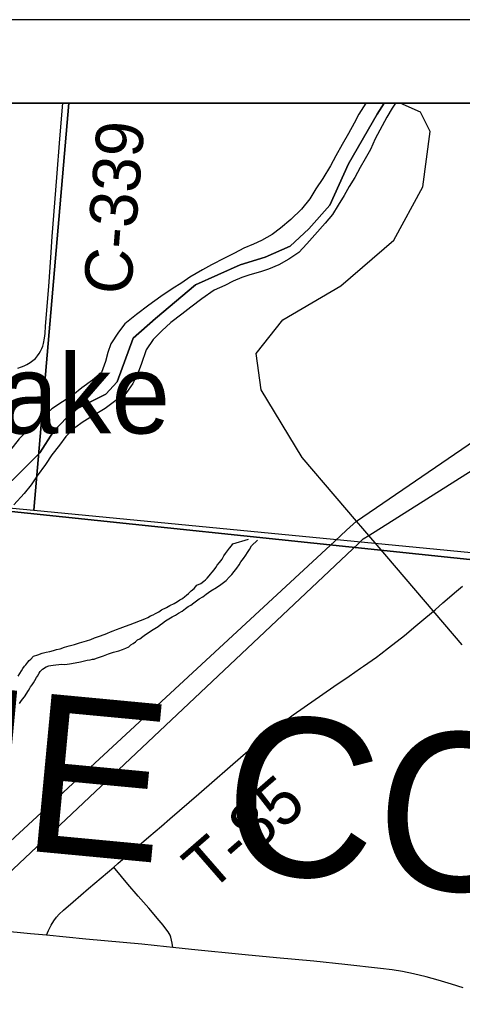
# Model space of a CAD drawing. Extents: x 0 to 34, y 0 to 22.
# Drawn here: x 25.311 to 25.841, y 19.186 to 20.362 of the extents above; entities that cross this region are included whole.
import ezdxf

# ---------------------------------------------------------------- set-up
doc = ezdxf.new("R2010")
doc.units = 0
for name, color, linetype in [('GM_X_County_Road', 7, 'Continuous'), ('GM_X_County_Road_Text', 7, 'Continuous'), ('GM_X_County_Text', 7, 'Continuous'), ('GM_X_Major_River', 7, 'Continuous'), ('GM_X_Minor_Lake_Text', 7, 'Continuous'), ('GM_X_Minor_River', 7, 'Continuous'), ('GM_X_Rail_Line', 7, 'Continuous'), ('GM_X_State_Route', 7, 'Continuous'), ('GM_X_Township_Road', 7, 'Continuous'), ('GM_X_Township_Road_Text', 7, 'Continuous'), ('SH_Border', 7, 'Continuous'), ('SH_Data', 7, 'Continuous')]:
    doc.layers.add(name, color=color, linetype=linetype)

msp = doc.modelspace()

# ---------------------------------------------------------------- linework, layer by layer
at = {"layer": 'GM_X_County_Road'}
for points in [[(25.3703, 20.2618), (24.3175, 20.2618), (24.2811, 19.8754), (24.2808, 19.8728), (25.3283, 19.7746)], [(26.3766, 20.2618), (25.3703, 20.2618), (25.3283, 19.7746), (26.3216, 19.6787)]]:
    msp.add_lwpolyline(points, close=True, dxfattribs=at)
msp.add_lwpolyline([(25.309, 19.9449), (25.3133, 19.9464), (25.3166, 19.9477), (25.3199, 19.9493), (25.3238, 19.9515), (25.3269, 19.9538), (25.3302, 19.9563), (25.3328, 19.9594), (25.3347, 19.9621), (25.3363, 19.9649), (25.3379, 19.9683), (25.3388, 19.971), (25.3397, 19.9744), (25.3409, 19.9806), (25.3416, 19.9861), (25.3423, 19.9948), (25.346, 20.0426), (25.3484, 20.0773), (25.3502, 20.1021), (25.3556, 20.1728), (25.3593, 20.219), (25.3631, 20.2618)], dxfattribs=at)
at = {"layer": 'GM_X_Major_River'}
for points in [[(25.7611, 20.2618), (25.7571, 20.2557), (25.7507, 20.2452), (25.7368, 20.219), (25.7311, 20.2066), (25.7248, 20.1953), (25.7188, 20.1849), (25.7124, 20.1729), (25.7057, 20.162), (25.6997, 20.1515), (25.6922, 20.1399), (25.6855, 20.1287), (25.6769, 20.1183), (25.6644, 20.1042), (25.655, 20.0934), (25.6452, 20.083), (25.6332, 20.075), (25.6213, 20.0684), (25.609, 20.0634), (25.5995, 20.0599), (25.5868, 20.0564), (25.5773, 20.0532), (25.5669, 20.0489), (25.5569, 20.0435), (25.5442, 20.0381), (25.5292, 20.0278), (25.516, 20.0179), (25.5055, 20.0095), (25.492, 19.9992), (25.4815, 19.9896), (25.471, 19.9792), (25.4627, 19.9665), (25.4565, 19.9492), (25.4521, 19.9375), (25.4465, 19.9262), (25.4382, 19.9143), (25.4262, 19.9059), (25.4134, 19.8963), (25.3995, 19.8879), (25.3872, 19.8803), (25.3771, 19.8733), (25.3666, 19.8629), (25.3588, 19.8525), (25.3497, 19.841), (25.3422, 19.8294), (25.3324, 19.8159), (25.3249, 19.8051), (25.3167, 19.7947), (25.3042, 19.7813)], [(25.7253, 20.2618), (25.7253, 20.2618), (25.717, 20.2487), (25.7114, 20.2378), (25.7047, 20.2255), (25.6971, 20.2124), (25.6896, 20.1989), (25.6832, 20.1869), (25.6741, 20.1719), (25.6658, 20.1592), (25.6586, 20.1473), (25.6484, 20.135), (25.6356, 20.1228), (25.6232, 20.1124), (25.6135, 20.1047), (25.6008, 20.0974), (25.5912, 20.0931), (25.5797, 20.0885), (25.5685, 20.0823), (25.5562, 20.0762), (25.5408, 20.0682), (25.53, 20.0624), (25.515, 20.0537), (25.5053, 20.0467), (25.4938, 20.0398), (25.4803, 20.0306)], [(25.4803, 20.0306), (25.466, 20.0203), (25.4512, 20.0089), (25.4373, 19.9979), (25.4294, 19.9878), (25.4203, 19.974), (25.4167, 19.9635), (25.4141, 19.9529), (25.4092, 19.9397), (25.3984, 19.9305), (25.3856, 19.9213), (25.3747, 19.9125), (25.3624, 19.9044), (25.3496, 19.896), (25.3356, 19.8827), (25.3224, 19.8713), (25.3108, 19.8602), (25.299, 19.8453), (25.2914, 19.8299), (25.2872, 19.8167), (25.2824, 19.8043), (25.2749, 19.7923), (25.2653, 19.788), (25.243, 19.7721)]]:
    msp.add_lwpolyline(points, dxfattribs=at)
at = {"layer": 'GM_X_Minor_River'}
for points in [[(25.4165, 19.6277), (25.4199, 19.6292), (25.4233, 19.6303), (25.4271, 19.6318), (25.4314, 19.6336), (25.4378, 19.6358), (25.4436, 19.6379), (25.4611, 19.6449), (25.4646, 19.6463), (25.468, 19.6482), (25.4711, 19.6496), (25.4738, 19.6511), (25.4776, 19.6533), (25.481, 19.6556), (25.4868, 19.6585), (25.491, 19.6607), (25.496, 19.6629), (25.5002, 19.6655), (25.5029, 19.6674), (25.5063, 19.6692), (25.509, 19.6714), (25.5109, 19.6729), (25.5132, 19.6752), (25.5163, 19.6782), (25.5202, 19.6811), (25.5233, 19.6849), (25.5282, 19.6871), (25.5317, 19.6897), (25.5336, 19.6916), (25.5356, 19.6934), (25.5379, 19.696), (25.5398, 19.6983), (25.5417, 19.7005), (25.5441, 19.7032), (25.546, 19.7062), (25.5476, 19.7088), (25.5503, 19.7122), (25.5534, 19.7163), (25.5557, 19.7201), (25.5577, 19.7231), (25.56, 19.7261), (25.5623, 19.7294), (25.5646, 19.7321), (25.5662, 19.7343), (25.5849, 19.7399)], [(25.447, 19.6151), (25.4497, 19.6173), (25.4524, 19.6196), (25.4551, 19.621), (25.4585, 19.6236), (25.462, 19.6259), (25.4651, 19.6281), (25.4689, 19.6307), (25.4769, 19.6355), (25.4792, 19.6374), (25.4823, 19.6396), (25.4858, 19.6422), (25.4896, 19.6448), (25.4938, 19.647), (25.4977, 19.6492), (25.5015, 19.6514), (25.5057, 19.654), (25.5099, 19.657), (25.513, 19.6596), (25.5161, 19.6611), (25.5195, 19.6637), (25.523, 19.6663), (25.526, 19.6685), (25.5303, 19.6711), (25.5345, 19.6744), (25.5402, 19.6782), (25.5468, 19.6822), (25.5521, 19.6859), (25.5583, 19.6908), (25.5621, 19.6945), (25.5652, 19.6979), (25.5679, 19.7012), (25.571, 19.7054), (25.5738, 19.7095), (25.5761, 19.7129), (25.5792, 19.717), (25.5819, 19.7208), (25.5839, 19.7242), (25.5862, 19.7279), (25.5886, 19.7321), (25.5958, 19.7389)], [(25.3093, 19.5763), (25.3113, 19.5793), (25.3136, 19.5827), (25.3152, 19.5853), (25.3171, 19.588), (25.3187, 19.5898), (25.321, 19.5928), (25.3225, 19.5947), (25.3245, 19.5966), (25.3279, 19.5999), (25.3329, 19.6018), (25.3383, 19.6036), (25.3428, 19.605), (25.3474, 19.6057), (25.3516, 19.6068), (25.3554, 19.6082), (25.3596, 19.6089), (25.3649, 19.6107), (25.3707, 19.6125), (25.3768, 19.614), (25.3829, 19.6161), (25.3912, 19.6183), (25.3966, 19.6201), (25.4008, 19.6219), (25.4046, 19.623), (25.4081, 19.6245), (25.4111, 19.6256), (25.4134, 19.6263), (25.4165, 19.6277)], [(25.3111, 19.5436), (25.3127, 19.5459), (25.3146, 19.5485), (25.3169, 19.5515), (25.322, 19.559), (25.3235, 19.5617), (25.3243, 19.5635), (25.3263, 19.5658), (25.3278, 19.568), (25.3294, 19.5711), (25.3313, 19.5744), (25.3325, 19.5763), (25.3345, 19.5797), (25.336, 19.5816), (25.3387, 19.5846), (25.3429, 19.5872), (25.346, 19.5883), (25.3486, 19.589), (25.3513, 19.5893), (25.3547, 19.5896), (25.3582, 19.59), (25.3616, 19.5903), (25.3654, 19.5902), (25.3711, 19.5909), (25.3775, 19.5919), (25.384, 19.5933), (25.392, 19.5951), (25.3958, 19.5958), (25.3985, 19.5965), (25.4004, 19.5965), (25.4031, 19.5976), (25.4069, 19.599), (25.4115, 19.6005), (25.4176, 19.6027), (25.4237, 19.6048), (25.4298, 19.6066), (25.4344, 19.6081), (25.4382, 19.6095), (25.442, 19.6114), (25.4443, 19.6136), (25.447, 19.6151)]]:
    msp.add_lwpolyline(points, dxfattribs=at)
at = {"layer": 'GM_X_Rail_Line'}
for p, q in [((25.729, 19.7446), (26.549, 20.2618)), ((25.739, 19.7329), (25.729, 19.7446)), ((25.8406, 19.6138), (25.739, 19.7329))]:
    msp.add_line(p, q, dxfattribs=at)
for points in [[(25.7145, 19.7615), (25.689, 19.7914), (25.6493, 19.838), (25.6002, 19.9189), (25.5944, 19.9622), (25.6262, 20.0027), (25.6955, 20.0431), (25.759, 20.098), (25.7937, 20.1616), (25.8023, 20.228), (25.7908, 20.2511), (25.7664, 20.2618)], [(25.7145, 19.7615), (26.2866, 20.1528), (26.4666, 20.2618)], [(25.6884, 19.7377), (25.7025, 19.7507), (25.7145, 19.7615)], [(25.729, 19.7446), (25.7218, 19.753), (25.7145, 19.7615)], [(22.5164, 16.9354), (22.6202, 16.9977), (23.2863, 17.3926), (23.9265, 17.9846), (25.2894, 19.3687), (25.6884, 19.7377)], [(22.5164, 16.4015), (22.604, 16.4732), (22.6804, 16.5359), (22.9964, 16.9071), (23.3912, 17.4049), (25.2192, 19.2663), (25.7166, 19.735)], [(25.7166, 19.735), (25.7222, 19.7403), (25.729, 19.7446)]]:
    msp.add_lwpolyline(points, dxfattribs=at)
at = {"layer": 'GM_X_State_Route'}
msp.add_lwpolyline([(25.8418, 19.2032), (25.8282, 19.2077), (25.8122, 19.2125), (25.7978, 19.2163), (25.7827, 19.2198), (25.7693, 19.2225), (25.7571, 19.2245), (25.743, 19.2264), (25.7003, 19.2311), (25.6633, 19.2349), (25.6187, 19.239), (25.581, 19.2428), (25.5167, 19.2491), (25.4946, 19.2513), (25.487, 19.2521), (25.4574, 19.2552), (25.3905, 19.2614), (25.3432, 19.266), (25.3244, 19.2678), (25.2879, 19.2712)], dxfattribs=at)
at = {"layer": 'GM_X_Township_Road'}
for points in [[(25.4239, 19.3477), (25.4288, 19.3519), (25.4659, 19.3839), (25.4811, 19.3968), (25.491, 19.4053), (25.5258, 19.4354), (25.5788, 19.4815), (25.599, 19.4989), (25.6125, 19.5099), (25.6252, 19.5198), (25.6387, 19.5297), (25.6871, 19.5636), (25.7055, 19.5762), (25.7193, 19.5857), (25.7229, 19.5882), (25.7381, 19.599), (25.7436, 19.603), (25.7525, 19.6099), (25.7716, 19.6249), (25.7855, 19.6363), (25.7974, 19.6463), (25.8083, 19.6556), (25.8176, 19.6638), (25.8256, 19.6707), (25.8317, 19.6759), (25.8411, 19.684)], [(25.3432, 19.266), (25.3459, 19.2718), (25.3488, 19.2781), (25.3521, 19.2835), (25.3553, 19.2878), (25.3586, 19.2914), (25.3636, 19.2961), (25.3754, 19.3062), (25.3938, 19.322), (25.4239, 19.3477)], [(25.4946, 19.2513), (25.4937, 19.2564), (25.493, 19.2601), (25.492, 19.2637), (25.4912, 19.2661), (25.4901, 19.2682), (25.4888, 19.2702), (25.4875, 19.2723), (25.483, 19.278), (25.4783, 19.2837), (25.4657, 19.2985), (25.4531, 19.3127), (25.4407, 19.3272), (25.4256, 19.3456), (25.4239, 19.3477)]]:
    msp.add_lwpolyline(points, dxfattribs=at)
at = {"layer": 'SH_Border'}
msp.add_lwpolyline([(25.7475, 20.2618), (24.3146, 20.2618), (24.3071, 20.185), (24.2795, 19.873), (25.1948, 19.7845), (25.2129, 19.7873), (25.2376, 19.8033), (25.3026, 19.8107), (25.3354, 19.8434), (25.3518, 19.8688), (25.3756, 19.8941), (25.4144, 19.9135), (25.4278, 19.9284), (25.4471, 19.9805), (25.474, 20.0043), (25.5216, 20.0446), (25.5753, 20.0684), (25.6051, 20.0774), (25.6349, 20.0908), (25.6572, 20.1116), (25.6826, 20.1399), (25.7049, 20.1891), (25.7392, 20.2487)], close=True, dxfattribs=at)
for points in [[(29.3164, 20.2618), (25.7475, 20.2618), (25.7392, 20.2487), (25.7049, 20.1891), (25.6826, 20.1399), (25.6572, 20.1116), (25.6349, 20.0908), (25.6051, 20.0774), (25.5753, 20.0684), (25.5216, 20.0446), (25.474, 20.0043), (25.4471, 19.9805), (25.4278, 19.9284), (25.4144, 19.9135), (25.3756, 19.8941), (25.3518, 19.8688), (25.3354, 19.8434), (25.3026, 19.8107), (25.2376, 19.8033), (25.2129, 19.7873), (25.1948, 19.7845), (25.8728, 19.7133), (27.3379, 19.575)], [(29.3164, 19.3886), (27.8281, 19.5287), (27.6909, 19.5416), (27.4869, 19.5609), (27.4759, 19.5619), (27.4554, 19.5638), (27.4405, 19.5654), (27.3379, 19.575), (25.8728, 19.7133), (25.1948, 19.7845), (24.2795, 19.873)]]:
    msp.add_lwpolyline(points, dxfattribs=at)
at = {"layer": 'SH_Data'}
for p, q in [((22.4164, 20.3618), (29.4164, 20.3618)), ((22.5164, 20.2618), (29.3164, 20.2618))]:
    msp.add_line(p, q, dxfattribs=at)
msp.add_lwpolyline([(29.3164, 19.3886), (29.3164, 20.2618), (24.3146, 20.2618), (24.3071, 20.185), (24.2795, 19.873), (25.1948, 19.7845), (25.8728, 19.7133), (27.3379, 19.575), (27.4405, 19.5654), (27.4554, 19.5638), (27.4759, 19.5619), (27.4869, 19.5609), (27.6909, 19.5416), (27.8281, 19.5287)], close=True, dxfattribs=at)
msp.add_lwpolyline([(29.3164, 19.3886), (27.8281, 19.5287), (27.6909, 19.5416), (27.4869, 19.5609), (27.4759, 19.5619), (27.4554, 19.5638), (27.4405, 19.5654), (27.3379, 19.575), (25.8728, 19.7133), (25.1948, 19.7845), (24.2795, 19.873)], dxfattribs=at)

# ---------------------------------------------------------------- texts
at = {"layer": 'GM_X_County_Road_Text'}
msp.add_text('C-339', height=0.05682, rotation=85.377, dxfattribs=at).set_placement((25.4441, 20.0315))
at = {"layer": 'GM_X_County_Text'}
msp.add_text('GREENE COUNTY', height=0.189394, rotation=354.6158, dxfattribs=at).set_placement((24.4144, 19.4527))
at = {"layer": 'GM_X_Minor_Lake_Text'}
msp.add_text('Medway Lake', height=0.094694, rotation=0.0032, dxfattribs=at).set_placement((24.7101, 19.8665))
at = {"layer": 'GM_X_Township_Road_Text'}
msp.add_text('T-85', height=0.05682, rotation=41.0184, dxfattribs=at).set_placement((25.5386, 19.3163))

doc.saveas('drawing.dxf')
